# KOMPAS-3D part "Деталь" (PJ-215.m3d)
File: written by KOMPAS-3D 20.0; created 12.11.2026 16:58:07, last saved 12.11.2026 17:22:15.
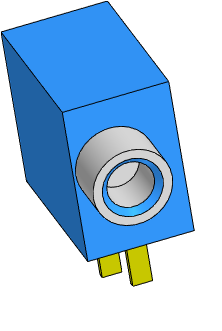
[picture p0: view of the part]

Document properties: Полное имя файла: D:\myProjects\Progect_esp32\box_compas\разъемы\PJ-215.m3d

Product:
- Part/product: Деталь
    Масса: 0.0116162
  - Body: Тело 1
      Масса: 0.0109577

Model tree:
1. Эскиз:1
2. Элемент выдавливания:1
     Расстояние 1 = 12.3
3. Эскиз:2  (with: Элемент выдавливания:1)
4. Элемент выдавливания:2
     Расстояние 1 = 4
5. Эскиз:3  (with: Элемент выдавливания:2)
6. Элемент выдавливания:3
     Расстояние 2 = 4
7. Фаска:1  (with: Элемент выдавливания:3)
     Угол = 45; Длина 1 = 0.5; Длина 2 = 0.5
8. Эскиз:4  (with: Элемент выдавливания:1)
9. Элемент выдавливания:4
     Расстояние 1 = 3.5
10. Эскиз:5  (with: Элемент выдавливания:4)
11. Элемент выдавливания:5
     Расстояние 2 = 1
